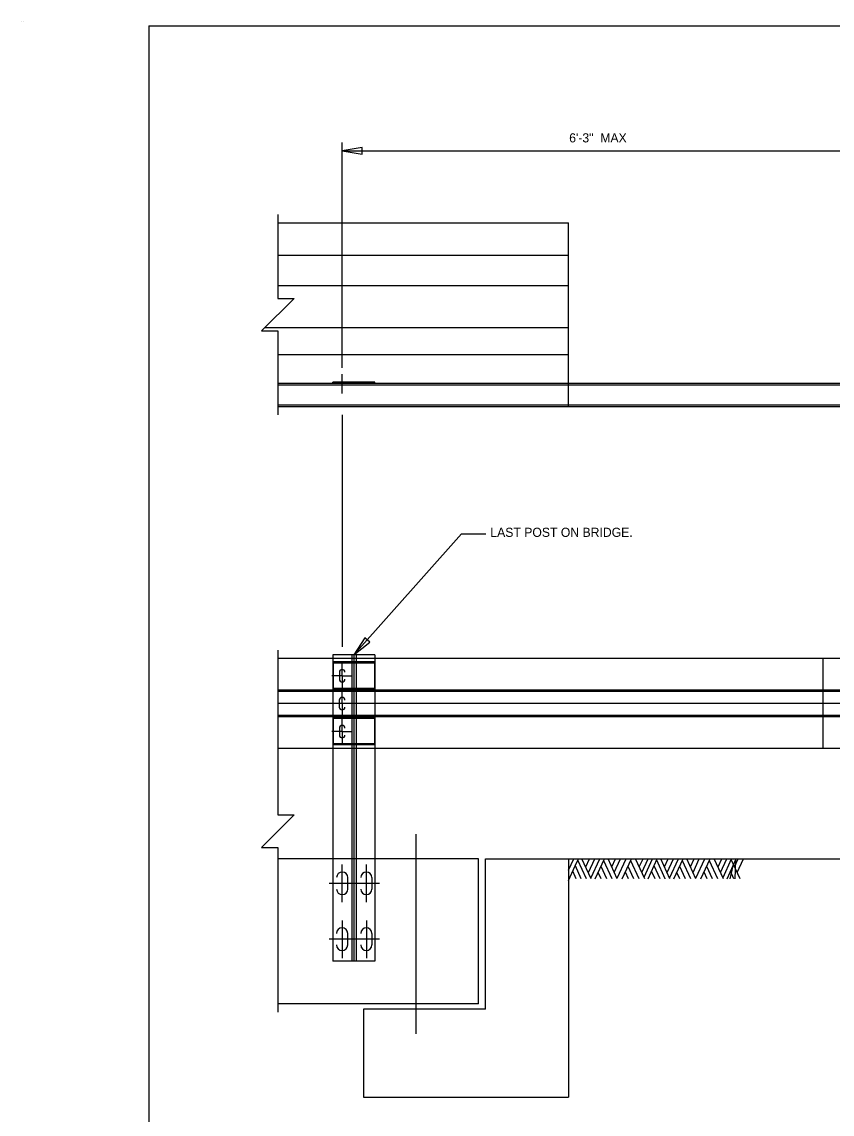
# Model space of a CAD drawing. Extents: x 809.7 to 842.4, y -901 to -880.3.
# Drawn here: x 809.66 to 819.41, y -893.49 to -880.35 of the extents above; entities that cross this region are included whole.
import ezdxf

# ---------------------------------------------------------------- set-up
doc = ezdxf.new("R2010")
doc.units = 0
for name, color, linetype in [('CONSTRUCTION LINE', 7, 'Continuous'), ('DIMENSION LINE', 7, 'Continuous'), ('EDGE OF PAVEMENT', 7, 'Continuous'), ('HIDDEN LINE', 7, 'Continuous'), ('OBJECT LINE', 7, 'Continuous'), ('REBAR', 7, 'Continuous'), ('STRUCTURES CENTERLINE', 7, 'Continuous'), ('STRUCTURES TEXT', 7, 'Continuous')]:
    doc.layers.add(name, color=color, linetype=linetype)

msp = doc.modelspace()

# ---------------------------------------------------------------- linework, layer by layer
at = {"layer": 'CONSTRUCTION LINE'}
for p, q in [((809.656, -880.349), (809.656, -880.349)), ((809.671, -880.349), (809.671, -880.349))]:
    msp.add_line(p, q, dxfattribs=at)
at = {"layer": 'DIMENSION LINE'}
for p, q in [((813.51, -884.51), (813.51, -881.801)), ((813.51, -881.9), (819.76, -881.9)), ((813.51, -885.077), (813.51, -887.865)), ((813.477, -888.173), (813.477, -888.256)), ((813.476, -888.508), (813.476, -888.591)), ((813.477, -888.845), (813.477, -888.928)), ((813.58, -890.78), (813.58, -890.643)), ((813.87, -890.78), (813.87, -890.643)), ((813.578, -891.453), (813.578, -891.315)), ((813.87, -891.453), (813.87, -891.315))]:
    msp.add_line(p, q, dxfattribs=at)
for centre, radius, start, end in [((813.511, -888.173), 0.0339, 360, 180), ((813.511, -888.256), 0.0339, 180, 0), ((813.51, -888.508), 0.0339, 360, 180), ((813.51, -888.591), 0.0339, 180, 0), ((813.511, -888.845), 0.0339, 360, 180), ((813.511, -888.928), 0.0339, 180, 0), ((813.512, -890.643), 0.0677, 0, 180), ((813.802, -890.643), 0.0677, 0, 180), ((813.512, -890.78), 0.0677, 180, 0), ((813.802, -890.78), 0.0677, 180, 0), ((813.51, -891.315), 0.0677, 0, 180), ((813.802, -891.315), 0.0677, 0, 180), ((813.51, -891.453), 0.0677, 180, 0), ((813.802, -891.453), 0.0677, 180, 0)]:
    msp.add_arc(centre, radius, start, end, dxfattribs=at)
at = {"layer": 'EDGE OF PAVEMENT'}
for points in [[(813.751, -881.86), (813.51, -881.9), (813.751, -881.94)], [(813.783, -887.757), (813.653, -887.964), (813.843, -887.81)]]:
    msp.add_lwpolyline(points, close=True, dxfattribs=at)
for points in [[(813.51, -881.9), (813.593, -881.9)], [(813.653, -887.964), (814.947, -886.507), (815.239, -886.507)]]:
    msp.add_lwpolyline(points, dxfattribs=at)
at = {"layer": 'HIDDEN LINE'}
for p, q in [((812.737, -882.766), (816.236, -882.766)), ((816.236, -884.978), (816.236, -882.766)), ((812.737, -883.155), (816.236, -883.155)), ((812.737, -883.521), (816.236, -883.521)), ((812.583, -884.025), (816.236, -884.025)), ((812.737, -884.352), (816.236, -884.352)), ((816.236, -884.701), (812.737, -884.701)), ((816.236, -884.72), (812.737, -884.72)), ((813.4, -884.701), (813.4, -884.685)), ((813.906, -884.685), (813.4, -884.685)), ((813.626, -884.701), (813.626, -884.685)), ((813.653, -884.701), (813.653, -884.685)), ((813.68, -884.701), (813.68, -884.685)), ((813.906, -884.701), (813.906, -884.685)), ((816.236, -884.958), (812.737, -884.958)), ((816.236, -884.978), (812.737, -884.978)), ((830.637, -884.958), (816.236, -884.958)), ((816.316, -888.006), (812.737, -888.006)), ((813.906, -887.964), (813.4, -887.964)), ((813.404, -888.047), (813.404, -888.385)), ((813.902, -888.047), (813.404, -888.047)), ((813.902, -888.063), (813.404, -888.063)), ((813.626, -887.964), (813.626, -891.646)), ((813.653, -887.964), (813.653, -891.646)), ((813.68, -887.964), (813.68, -891.646)), ((813.902, -888.047), (813.902, -888.385)), ((813.906, -887.964), (813.906, -891.646)), ((819.296, -888.006), (819.296, -889.089)), ((813.51, -888.139), (813.51, -888.139)), ((813.51, -888.139), (813.51, -888.139)), ((813.51, -888.139), (813.51, -888.139)), ((813.51, -888.139), (813.51, -888.139)), ((813.51, -888.29), (813.51, -888.29)), ((813.51, -888.29), (813.51, -888.29)), ((813.51, -888.29), (813.51, -888.29)), ((813.51, -888.29), (813.51, -888.29)), ((813.4, -888.389), (812.737, -888.389)), ((813.4, -888.404), (812.737, -888.404)), ((813.906, -888.389), (813.4, -888.389)), ((813.906, -888.404), (813.4, -888.404)), ((813.902, -888.369), (813.404, -888.369)), ((813.902, -888.385), (813.404, -888.385)), ((813.51, -888.474), (813.51, -888.474)), ((813.51, -888.474), (813.51, -888.474)), ((813.51, -888.474), (813.51, -888.474)), ((813.51, -888.474), (813.51, -888.474)), ((816.316, -888.389), (813.906, -888.389)), ((816.316, -888.404), (813.906, -888.404)), ((834.183, -888.389), (816.316, -888.389)), ((834.183, -888.404), (816.316, -888.404)), ((813.51, -888.55), (813.51, -888.55)), ((813.51, -888.55), (813.51, -888.55)), ((813.51, -888.55), (813.51, -888.55)), ((813.51, -888.55), (813.51, -888.55)), ((813.4, -888.694), (812.737, -888.694)), ((813.4, -888.71), (812.737, -888.71)), ((813.906, -888.694), (813.4, -888.694)), ((813.906, -888.71), (813.4, -888.71)), ((813.404, -888.714), (813.404, -889.047)), ((813.902, -888.714), (813.404, -888.714)), ((813.902, -888.729), (813.404, -888.729)), ((813.51, -888.625), (813.51, -888.625)), ((813.51, -888.625), (813.51, -888.625)), ((813.51, -888.625), (813.51, -888.625)), ((813.51, -888.625), (813.51, -888.625)), ((813.902, -888.714), (813.902, -889.047)), ((816.316, -888.694), (813.906, -888.694)), ((816.316, -888.71), (813.906, -888.71)), ((834.183, -888.694), (816.316, -888.694)), ((834.183, -888.71), (816.316, -888.71)), ((813.51, -888.811), (813.51, -888.811)), ((813.51, -888.811), (813.51, -888.811)), ((813.51, -888.811), (813.51, -888.811)), ((813.51, -888.811), (813.51, -888.811)), ((813.51, -888.886), (813.51, -888.886)), ((813.51, -888.886), (813.51, -888.886)), ((813.51, -888.886), (813.51, -888.886)), ((813.51, -888.886), (813.51, -888.886)), ((813.51, -888.962), (813.51, -888.962)), ((813.51, -888.962), (813.51, -888.962)), ((813.51, -888.962), (813.51, -888.962)), ((813.51, -888.962), (813.51, -888.962)), ((816.316, -889.089), (812.737, -889.089)), ((813.902, -889.032), (813.404, -889.032)), ((813.902, -889.047), (813.404, -889.047)), ((815.153, -890.417), (812.737, -890.417)), ((815.153, -892.163), (815.153, -890.417)), ((815.236, -892.226), (815.236, -890.417)), ((815.236, -890.417), (816.316, -890.417)), ((816.236, -890.417), (816.236, -893.282)), ((816.236, -890.554), (816.299, -890.417)), ((816.236, -890.676), (816.316, -890.503)), ((816.316, -890.631), (816.287, -890.566)), ((813.906, -891.646), (813.4, -891.646)), ((815.153, -892.163), (812.737, -892.163)), ((815.236, -892.226), (813.768, -892.226)), ((813.768, -892.226), (813.768, -893.282)), ((814.403, -892.163), (814.403, -892.163)), ((814.403, -892.163), (814.403, -892.163)), ((814.403, -892.163), (814.403, -892.163)), ((814.403, -892.163), (814.403, -892.163)), ((813.768, -893.282), (816.236, -893.282))]:
    msp.add_line(p, q, dxfattribs=at)
at = {"layer": 'OBJECT LINE'}
for p, q in [((830.637, -884.701), (816.236, -884.701)), ((822.502, -884.72), (816.236, -884.72)), ((830.683, -884.978), (816.236, -884.978)), ((819.542, -888.006), (816.316, -888.006)), ((819.542, -889.089), (816.316, -889.089)), ((816.316, -890.503), (816.356, -890.417)), ((816.316, -890.417), (830.637, -890.417)), ((816.451, -890.657), (816.348, -890.434)), ((816.508, -890.657), (816.397, -890.417)), ((816.442, -890.514), (816.487, -890.417)), ((816.474, -890.583), (816.55, -890.417)), ((816.504, -890.649), (816.612, -890.417)), ((816.556, -890.657), (816.668, -890.417)), ((816.759, -890.657), (816.658, -890.439)), ((816.822, -890.657), (816.711, -890.417)), ((816.756, -890.514), (816.8, -890.417)), ((816.786, -890.58), (816.861, -890.417)), ((816.819, -890.65), (816.927, -890.417)), ((816.882, -890.657), (816.993, -890.417)), ((817.085, -890.657), (816.983, -890.439)), ((817.153, -890.657), (817.042, -890.417)), ((817.087, -890.515), (817.132, -890.417)), ((817.118, -890.582), (817.195, -890.417)), ((817.145, -890.639), (817.247, -890.417)), ((817.193, -890.657), (817.303, -890.417)), ((817.398, -890.657), (817.296, -890.434)), ((817.455, -890.657), (817.345, -890.417)), ((817.389, -890.514), (817.434, -890.417)), ((817.421, -890.583), (817.498, -890.417)), ((817.452, -890.649), (817.56, -890.417)), ((817.503, -890.657), (817.616, -890.417)), ((817.706, -890.657), (817.605, -890.439)), ((817.769, -890.657), (817.659, -890.417)), ((817.703, -890.514), (817.747, -890.417)), ((817.734, -890.58), (817.809, -890.417)), ((817.767, -890.65), (817.875, -890.417)), ((817.829, -890.657), (817.941, -890.417)), ((818.032, -890.657), (817.931, -890.439)), ((818.1, -890.657), (817.989, -890.417)), ((818.035, -890.515), (818.08, -890.417)), ((818.065, -890.581), (818.142, -890.417)), ((818.094, -890.643), (818.198, -890.417)), ((818.143, -890.657), (818.254, -890.417)), ((818.299, -890.657), (818.188, -890.417)), ((818.233, -890.514), (818.278, -890.417)), ((818.242, -890.657), (818.247, -890.435)), ((818.265, -890.583), (818.342, -890.417)), ((816.389, -890.657), (816.317, -890.501)), ((816.627, -890.657), (816.592, -890.58)), ((816.694, -890.657), (816.626, -890.508)), ((816.955, -890.657), (816.919, -890.578)), ((817.019, -890.657), (816.951, -890.509)), ((817.276, -890.657), (817.234, -890.567)), ((817.336, -890.657), (817.265, -890.501)), ((817.389, -890.515), (817.397, -890.498)), ((817.389, -890.515), (817.397, -890.498)), ((817.574, -890.657), (817.539, -890.58)), ((817.641, -890.657), (817.573, -890.508)), ((817.902, -890.657), (817.866, -890.578)), ((817.967, -890.657), (817.898, -890.509)), ((818.18, -890.657), (818.216, -890.501)), ((818.226, -890.657), (818.185, -890.567)), ((816.328, -890.657), (816.316, -890.631)), ((817.398, -890.657), (817.397, -890.653)), ((817.398, -890.657), (817.397, -890.653))]:
    msp.add_line(p, q, dxfattribs=at)
for points in [[(812.737, -882.668), (812.737, -883.677), (812.932, -883.677), (812.541, -884.067), (812.737, -884.067), (812.737, -885.076)], [(812.737, -887.908), (812.737, -889.889), (812.932, -889.889), (812.541, -890.28), (812.737, -890.28), (812.737, -892.261)]]:
    msp.add_lwpolyline(points, dxfattribs=at)
at = {"layer": 'REBAR'}
for q in [(811.184, -900.908), (842.1, -880.399)]:
    msp.add_line((811.186, -880.398), q, dxfattribs=at)
at = {"layer": 'STRUCTURES CENTERLINE'}
for p, q in [((813.51, -884.819), (813.51, -884.586)), ((813.511, -888.215), (813.511, -888.051)), ((813.511, -888.215), (813.388, -888.215)), ((813.51, -888.215), (813.51, -888.379)), ((813.511, -888.215), (813.633, -888.215)), ((813.51, -888.549), (813.51, -888.379)), ((816.316, -888.549), (812.737, -888.549)), ((813.51, -888.549), (813.51, -888.714)), ((834.271, -888.549), (816.316, -888.549)), ((813.511, -888.886), (813.511, -888.714)), ((813.511, -888.886), (813.388, -888.886)), ((813.51, -888.886), (813.51, -889.05)), ((813.511, -888.886), (813.633, -888.886)), ((814.403, -892.523), (814.403, -890.12)), ((813.512, -890.938), (813.512, -890.486)), ((813.802, -890.938), (813.802, -890.486)), ((813.653, -890.712), (813.355, -890.712)), ((813.959, -890.712), (813.653, -890.712)), ((813.51, -891.158), (813.51, -891.61)), ((813.802, -891.158), (813.802, -891.61)), ((813.959, -891.384), (813.353, -891.384))]:
    msp.add_line(p, q, dxfattribs=at)
at = {"layer": 'STRUCTURES TEXT'}
msp.add_line((813.4, -887.964), (813.4, -891.646), dxfattribs=at)

# ---------------------------------------------------------------- texts
for s, height, p in [('6\'-3"  MAX', 0.1098, (816.243, -881.799)), ('LAST POST ON BRIDGE.', 0.10979, (815.294, -886.544))]:
    msp.add_text(s, height=height, dxfattribs=at).set_placement(p)

doc.saveas('drawing.dxf')
